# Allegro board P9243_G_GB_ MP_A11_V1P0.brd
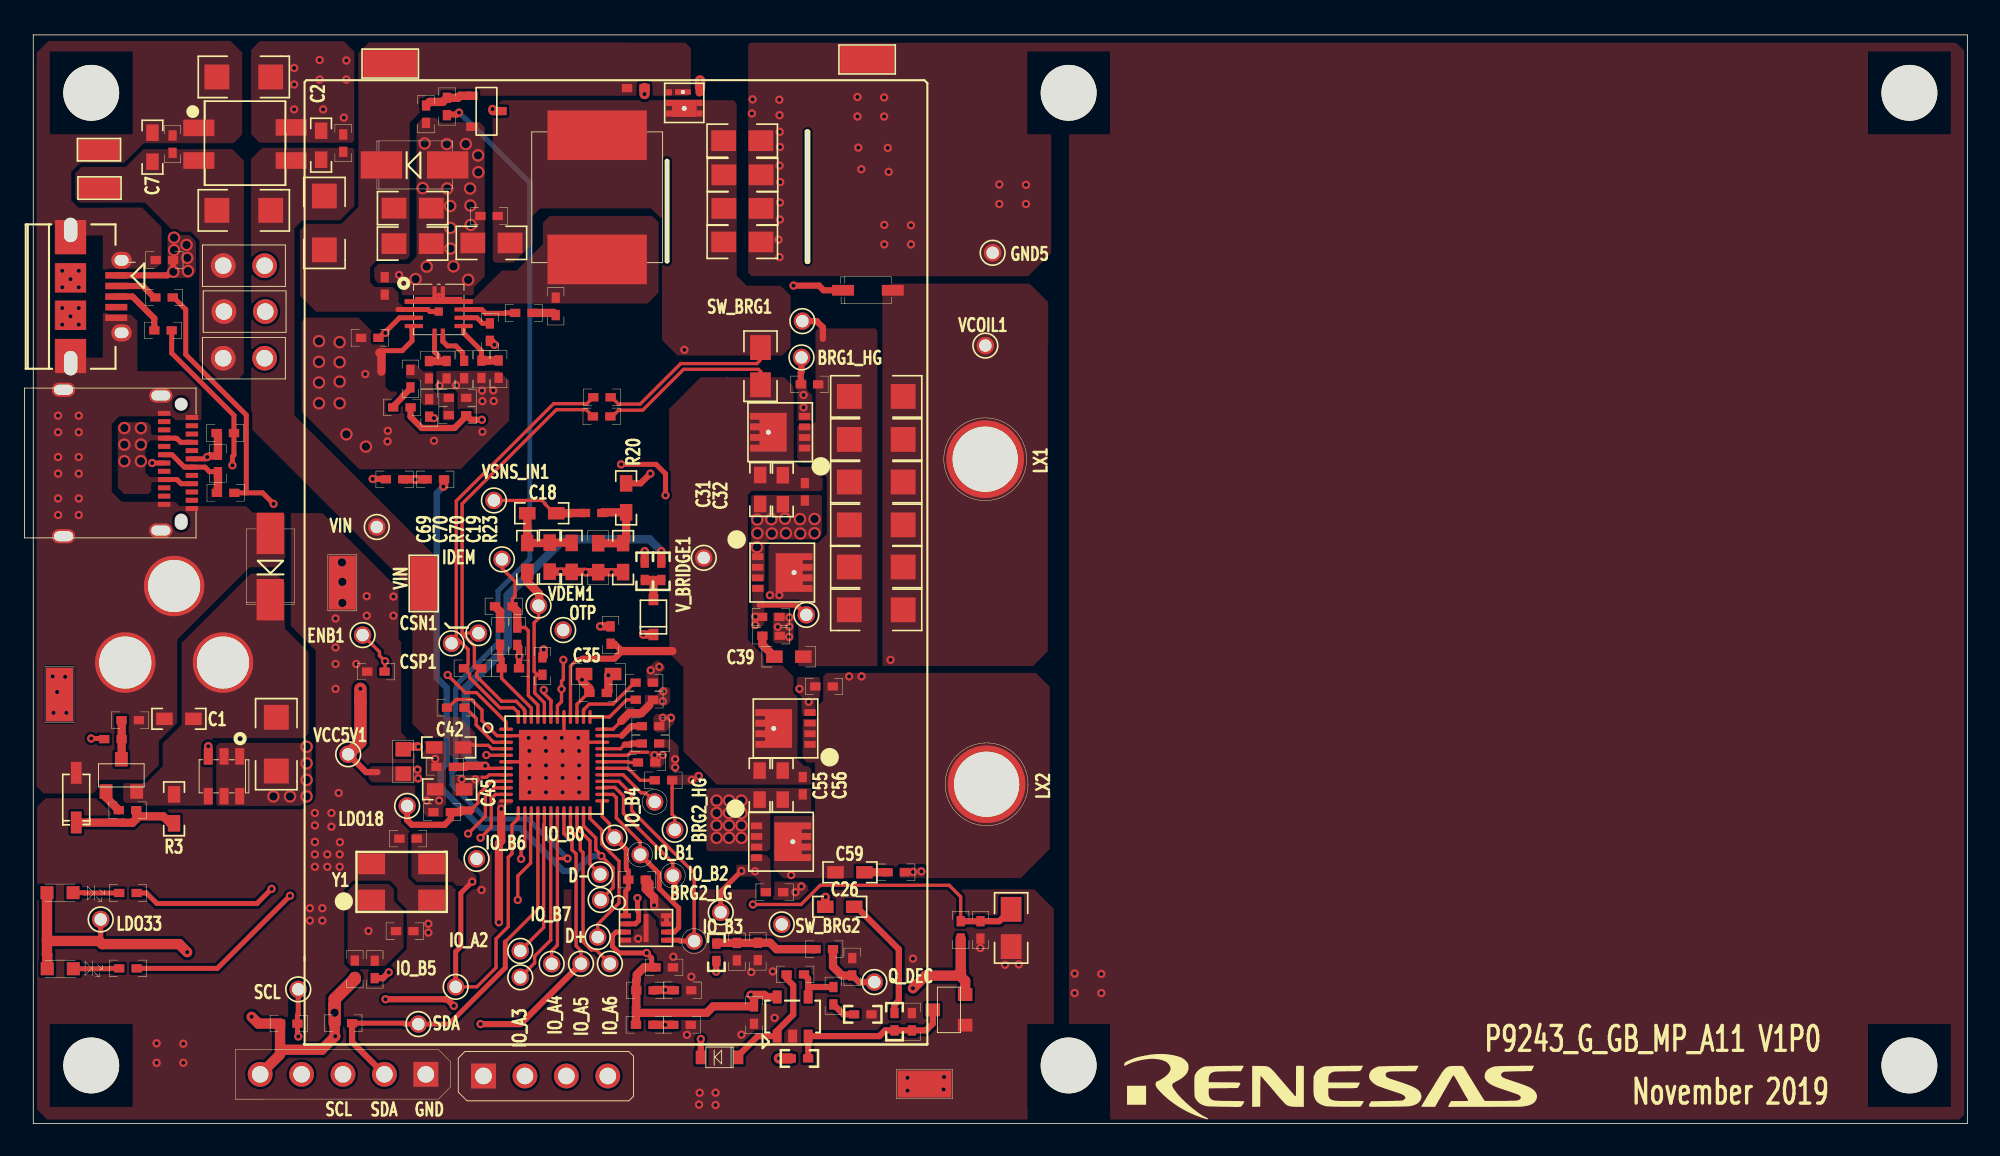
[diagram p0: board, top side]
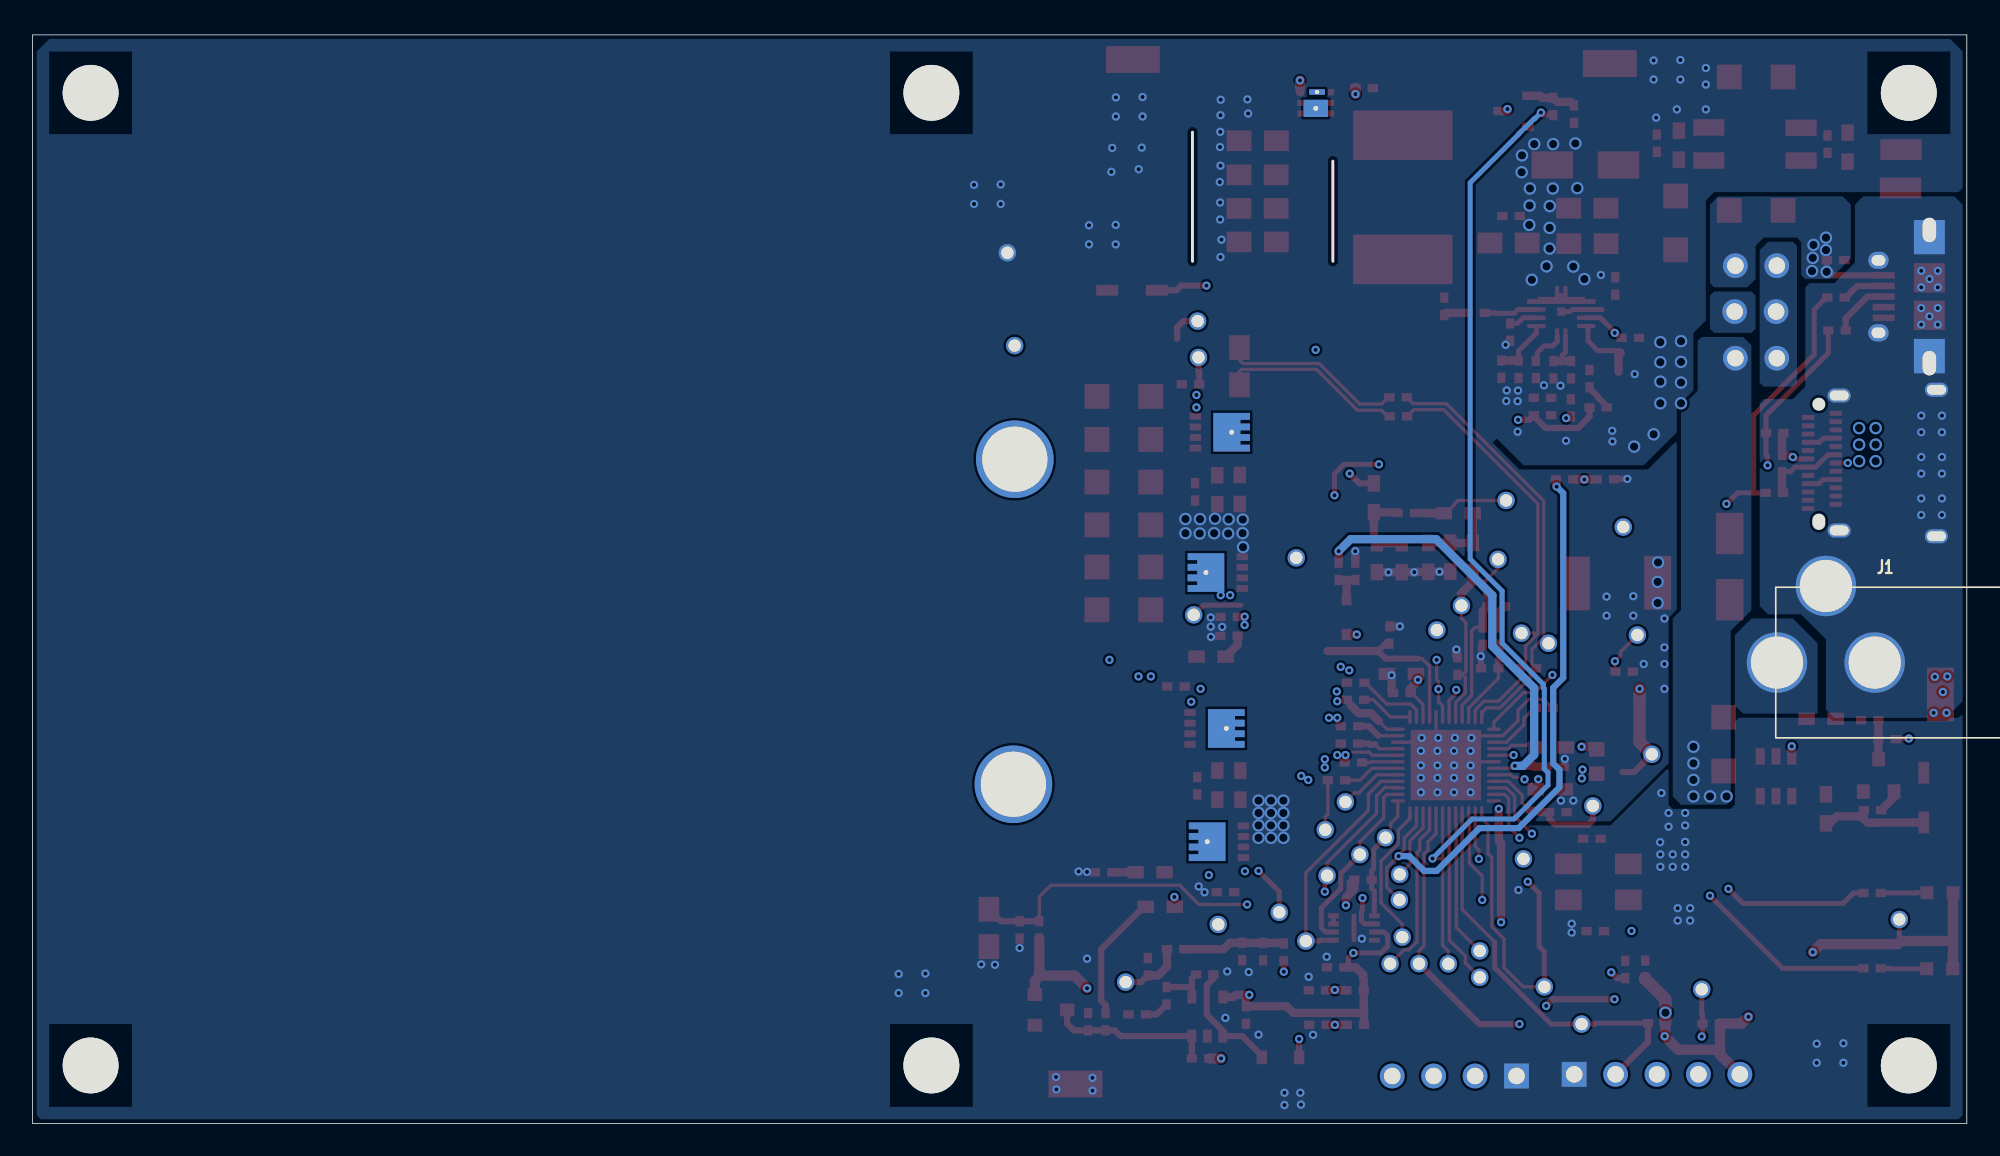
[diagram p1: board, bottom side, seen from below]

Outline 118.62 x 66.8 mm; copper layers: TOP, L1, L2, BOTTOM. Coordinates in mm from the lower left corner of the outline.
Outline path: 0,66.8 0,0 118.62,0 118.62,66.8 0,66.8

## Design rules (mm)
constraint set DEFAULT: min track width 0.152
nets with their own width: min track width 0.508; nets GND

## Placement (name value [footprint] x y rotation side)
BK_VIN  TP  [TEST_PT_SM_135X70]  21.9 65.04 0 top
BRG1_HG  PTH_TP  [TEST_PT30DPAD]  47.12 47.01 0 top
BRG1_LG  PTH_TP  [TEST_PT30DPAD]  47.41 31.21 0 top
BRG2_HG  PTH_TP  [TEST_PT30DPAD]  39.34 18.02 0 top
BRG2_LG  PTH_TP  [TEST_PT30DPAD]  42.16 12.95 0 top
C1  0.1uF  [0603]  8.93 24.83 180 top
C2  10uF  [0603]  17.66 60.03 270 top
C3  0.1uF  [0402]  19.01 60.16 270 top
C4  22uF  [0805]  23.27 56.17 0 top
C5  0.1uF  [0402]  21.56 51.4 270 top
C6  22uF  [0805]  23.27 53.99 0 top
C7  10uF  [0603]  7.31 59.91 270 top
C8  0.1uF  [0402]  8.54 60.1 90 top
C9  0.1uF  [0402]  32.04 50.14 270 top
C10  22uF  [0805]  28.1 54.04 180 top
C11  0.1uF  [0402]  27.95 55.68 180 top
C12  0.1uF  [0402]  28.01 48.56 270 top
C13  NP  [0402]  27.49 46.28 270 top
C14  NP  [0402]  25.35 46.26 270 top
C15  0.1uF  [0402]  26.43 46.27 270 top
C16  0.1uF  [0402]  22.16 39.53 0 top
C18  22nF  [0603]  31.19 37.44 180 top
C19  5.6nF  [0603]  34.65 34.72 90 top
C20  680p  [0402]  31.23 28.07 270 top
C21  22nF  [0402]  28.86 31.73 180 top
C22  22uF  [0805]  43.5 56.15 0 top
C23  22uF  [0805]  43.5 58.21 0 top
C24  22uF  [0805]  43.48 60.31 0 top
C25  22uF  [0805]  43.49 54.1 0 top
C26  220pF  [0603]  49.46 13.29 0 top
C27  5.6nF  [0402]  43.15 10.54 90 top
C28  56pF  [0402]  29.26 27.93 180 top
C29  680pF  [0402]  29.68 29.9 270 top
C30  0.1uF  [0402]  35.41 29.97 270 top
C31  10uF  [0603]  44.58 38.9 90 top
C32  10uF  [0603]  45.97 38.89 90 top
C33  0.1uF  [0402]  47.32 38.76 90 top
C34  0.1uF  [0402]  34.64 26.42 180 top
C35  10uF  [0603]  34.67 27.58 180 top
C36  2.2nF  [0402]  50.23 9.61 270 top
C37  1uF  [0402]  26.95 27.93 180 top
C38  0.1uF  [0402]  37.48 26 0 top
C39  22nF  [0603]  46.34 28.65 0 top
C40  0.1uF  [0402]  44.2 6.65 90 top
C42  10uF  [0603]  25.48 23.07 0 top
C43  1uF  [0402]  25.91 25.51 180 top
C44  100nF  [1206]  51.7 44.61 180 top
C45  10uF  [0603]  25.54 20.5 0 top
C46  0.1uF  [0402]  37.62 22.15 180 top
C47  100nF  [1206]  51.7 41.97 180 top
C48  100nF  [1206]  51.7 39.36 180 top
C49  100nF  [1206]  51.7 36.73 180 top
C50  1uF  [0402]  25.26 21.89 0 top
C51  100nF  [1206]  51.7 34.14 180 top
C52  NP  [1206]  51.7 31.52 180 top
C53  1uF  [0402]  25.08 19.1 0 top
C55  10uF  [0603]  44.55 20.76 90 top
C56  10uF  [0603]  45.96 20.76 90 top
C57  0.1uF  [0402]  47.19 20.72 90 top
C59  22nF  [0603]  50.09 15.41 180 top
C60  18pF  [0402]  22.99 17.48 0 top
C61  18pF  [0402]  22.78 11.8 180 top
C66  0.1uF  [0402]  38.7 9.58 180 top
C67  0.1uF  [0402]  58.09 11.88 90 top
C68  0.1uF  [0402]  8.05 52.98 180 top
C69  22nF  [0603]  30.29 34.73 270 top
C70  5.6nF  [0603]  31.67 34.75 90 top
C71  NP  [0402]  23.14 45.7 270 top
C72  0.1uF  [0402]  50.88 6.69 180 top
CSN1  PTH_TP  [TEST_PT30DPAD]  27.3 30.09 0 top
CSP1  PTH_TP  [TEST_PT30DPAD]  25.65 29.46 0 top
D1  DDZ20BSF-7  [SOD123]  2.64 19.99 270 top
D2  BAV21W-7-F  [SOD123]  51.19 51.13 180 top
D4  1N4148  [SOD-323]  43.23 4.05 180 top
D5  SMAJ20CA-13-F  [SMAJ20CA]  14.54 34.17 270 top
D6  SMAJ20CA-13-F  [SMAJ20CA]  23.39 58.82 180 top
D8  SBAT54SLT1G  [SOT-23]  57.15 6.03 90 top
D9  PMEG4005EJ  [SOD323F]  38.04 31.08 90 top
D+  PTH_TP  [TEST_PT30DPAD]  34.62 11.44 0 top
D-  PTH_TP  [TEST_PT30DPAD]  34.78 15.28 0 top
ENB1  PTH_TP  [TEST_PT30DPAD]  20.2 29.97 0 top
GND  TP  [TEST_PT_SM100X50]  4.03 59.76 90 top
GND1  TP  [TEST_PT_SM_135X70]  51.14 65.29 0 top
GND2  TP  [TEST_PT_SM_135X70]  18.96 33.18 90 top
GND3  TP  [TEST_PT_SM_135X70]  54.66 2.42 0 top
GND4  TP  [TEST_PT_SM_135X70]  1.61 26.32 90 top
GND5  PTH_TP  [TEST_PT30DPAD]  58.84 53.43 0 top
IDEM  PTH_TP  [TEST_PT30DPAD]  28.75 34.62 0 top
IO_A2  PTH_TP  [TEST_PT30DPAD]  29.87 10.59 0 top
IO_A3  PTH_TP  [TEST_PT30DPAD]  29.87 8.97 0 top
IO_A4  PTH_TP  [TEST_PT30DPAD]  31.79 9.79 180 top
IO_A5  PTH_TP  [TEST_PT30DPAD]  33.59 9.8 180 top
IO_A6  PTH_TP  [TEST_PT30DPAD]  35.37 9.8 180 top
IO_B0  PTH_TP  [TEST_PT30DPAD]  35.65 17.54 0 top
IO_B1  PTH_TP  [TEST_PT30DPAD]  37.22 16.5 90 top
IO_B2  PTH_TP  [TEST_PT30DPAD]  39.23 15.21 90 top
IO_B3  PTH_TP  [TEST_PT30DPAD]  40.53 11.19 90 top
IO_B4  PTH_TP  [TEST_PT30DPAD]  38.11 19.73 90 top
IO_B5  PTH_TP  [TEST_PT30DPAD]  25.91 8.38 180 top
IO_B6  PTH_TP  [TEST_PT30DPAD]  27.19 16.24 0 top
IO_B7  PTH_TP  [TEST_PT30DPAD]  34.8 13.72 0 top
J1  AC_Adapter  [CONN_POWER_JACK5_5MM]  11.64 28.28 180 bottom
J2  USB Type C  [USB-C12401610E4]  9.07 40.53 270 top
J3  SIP con  [SIP-4]  27.62 2.91 0 top
J4  68000-105HLF  [SIP5]  24.08 3.01 180 top
J11  5P  [USB_MICRO_AB]  2.29 50.74 270 top
J13  JMP  [SIP2]  14.19 46.96 180 top
J14  JMP  [SIP2]  14.23 49.82 180 top
J15  JMP  [SIP2]  14.19 52.64 180 top
L1  ACM4520  [EMI_TDK_ACM4520L]  12.98 60.16 90 top
L2  TBD  [1206]  17.86 55.26 270 top
L3  10uH  [5X5-10X10]  34.59 56.83 90 top
L4  4.7uH  [L0603]  22.69 22.21 90 top
LDO18  PTH_TP  [TEST_PT30DPAD]  22.93 19.48 0 top
LDO33  PTH_TP  [TEST_PT30DPAD]  4.14 12.52 0 top
LED1  LED  [0603_DIODE]  1.64 14.16 180 top
LED2  LED  [0603_DIODE]  1.66 9.49 180 top
LX1  PTH_TP  [TP_TXCOIL]  58.38 40.76 0 top
LX2  PTH_TP  [TP_TXCOIL]  58.47 20.81 0 top
NOREF  -  [unnamed]  63.5 63.25 0 top
NOREF#2  -  [#2]  0 0 90 top
NOREF#3  -  [unnamed]  63.5 3.56 0 top
NOREF#4  -  [#2]  0 66.64 0 top
NOREF#5  -  [#2]  66.37 -0.28 0 top
NOREF#6  -  [#2]  28.02 19.37 0 top
NOREF#7  -  [#2]  39.45 18.86 90 top
NOREF#8  -  [unnamed]  115.06 3.56 0 top
NOREF#9  -  [unnamed]  3.56 3.56 0 top
NOREF#10  -  [unnamed]  115.06 63.25 0 top
NOREF#11  -  [unnamed]  3.56 63.25 0 top
OTP  PTH_TP  [TEST_PT30DPAD]  32.5 30.28 0 top
Q1  SIA449DJ-T1-GE3  [SC70_6LD_FET]  39.93 62.63 180 top
Q2  Si3417  [SOT-23-6]  11.7 21.3 180 top
Q4  2N7002  [SOT23_3]  27.8 62.13 0 top
Q5  DMG7430LFG  [POWERDI3333_8LD_FET]  45.81 42.42 180 top
Q6  DMG7430LFG  [POWERDI3333_8LD_FET]  45.93 33.8 0 top
Q7  DMG7430LFG  [POWERDI3333_8LD_FET]  46.14 24.24 180 top
Q8  DMG7430LFG  [POWERDI3333_8LD_FET]  45.86 17.29 0 top
Q10  MMBT4403/SOT  [SOT-23]  4.47 20.37 0 top
Q_DEC  PTH_TP  [TEST_PT30DPAD]  51.59 8.67 0 top
R1  0  [1206]  14.91 23.27 270 top
R2  0  [1206]  12.92 56.03 0 top
R3  150  [0603]  8.64 19.3 270 top
R4  100K  [0402]  36.96 63.54 0 top
R5  10k  [0402]  5.78 19.22 180 top
R6  91K  [0402]  5.95 24.75 0 top
R7  10  [0402]  30.09 49.74 0 top
R8  100K  [0402]  24.09 61.93 270 top
R9  0  [1206]  12.92 64.22 0 top
R11  150K  [0402]  26.02 43.46 180 top
R12  30k  [0402]  24.27 46.25 270 top
R13  18K  [0402]  24.28 43.91 270 top
R14  3.3K  [0402]  24.66 39.53 180 top
R15  30k  [0402]  28.54 46.29 270 top
R16  5.1K  [0402]  26.02 44.53 0 top
R18  0  [0402]  11.78 42.37 0 top
R19  10k  [0402]  34.37 37.46 0 top
R20  2.4K  [0603]  36.36 38.39 270 top
R21  0  [0402]  11.8 38.7 0 top
R22  10  [0402]  34.88 44.56 0 top
R23  200K  [0603]  36.17 34.72 90 top
R24  NP  [0402]  11.33 40.5 270 top
R25  10  [0402]  34.86 43.39 0 top
R26  0.02  [0805]  44.6 46.47 270 top
R28  10k  [0402]  28.63 29.91 90 top
R30  18.2k  [0402]  44.44 10.55 90 top
R31  2K  [0402]  48.51 10.69 0 top
R35  22  [0402]  37.47 27.05 0 top
R36  100K  [0402]  47.61 45.36 0 top
R38  22  [0402]  41.9 10.5 270 top
R39  0  [0402]  45.25 29.93 180 top
R40  22  [0402]  37.86 24.38 0 top
R41  1K  [0402]  21.01 27.73 0 top
R42  100K  [0402]  45.23 31.08 180 top
R43  1K  [0402]  5.81 14.14 0 top
R44  22  [0402]  38.65 21.06 0 top
R45  100K  [0402]  48.5 26.82 180 top
R46  680  [0402]  5.81 9.52 0 top
R47  22  [0402]  37.86 23.31 0 top
R48  100K  [0402]  45.46 14.19 0 top
R49  0  [0402]  52.93 15.41 180 top
R50  5.1K  [0402]  19.02 6.15 0 top
R52  5.1K  [0402]  15.67 6.13 0 top
R57  100K  [0402]  37.03 14.96 180 top
R58  20K  [0402]  37.52 8.17 180 top
R59  10k  [0402]  39.82 8.17 180 top
R60  10k  [0402]  56.88 11.88 90 top
R61  10k  [0402]  37.5 6.05 180 top
R62  10k  [0402]  39.79 6.05 180 top
R68  0  [0402]  7.96 48.67 180 top
R69  0  [0402]  8.02 50.68 180 top
R70  47k  [0603]  33.02 34.73 90 top
R79  NP  [0402]  22.61 43.94 0 top
R80  0  [0402]  4.89 23.58 0 top
R82  10k  [0402]  53.89 6.24 270 top
R84  1M  [0402]  20.94 9.45 270 top
R85  5.1K  [0402]  19.72 9.46 90 top
R88  0  [0402]  25.37 62.41 90 top
R93  40.2k  [0402]  46.74 9.14 0 top
R94  10k  [0402]  49.07 7.84 270 top
R95  10k  [0402]  20.64 48.21 0 top
R98  220  [0402]  52.82 6.24 270 top
R99  4.7K  [0402]  38.52 33.88 270 top
R100  825  [0402]  37.5 33.88 270 top
R101  10k  [0402]  46.99 3.99 180 top
SCL  PTH_TP  [TEST_PT30DPAD]  16.25 8.23 0 top
SDA  PTH_TP  [TEST_PT30DPAD]  23.62 6.1 0 top
SW_BRG1  PTH_TP  [TEST_PT30DPAD]  47.17 49.24 0 top
SW_BRG2  PTH_TP  [TEST_PT30DPAD]  45.91 12.21 0 top
T1  TP  [8X250UNPLATED]  38.87 55.98 90 top
T2  TP  [8X320UNPLATED]  47.49 56.87 90 top
TH_COIL1  NP  [0805]  59.97 12 270 top
U1  MP2229  [MP_2229]  24.87 49.95 0 top
U3  P9243-GB  [SOCKETQFN_48_6X6_0P4]  31.95 21.99 0 top
U4  MCP6021  [SOT23-5]  46.57 6.56 90 top
U7  W25X40CLUXIG  [USON_2X3_8LD]  37.58 11.99 0 top
V_BRIDGE1  PTH_TP  [TEST_PT30DPAD]  41.12 34.71 0 top
VCC5V1  PTH_TP  [TEST_PT30DPAD]  19.32 22.65 0 top
VCOIL1  PTH_TP  [TEST_PT30DPAD]  58.39 47.73 0 top
VDEM1  PTH_TP  [TEST_PT30DPAD]  30.99 31.78 0 top
VIN  PTH_TP  [TEST_PT30DPAD]  21.07 36.6 0 top
VIN1  TP  [TEST_PT_SM_135X70]  23.95 33.14 90 top
VIN_SEL  TP  [TEST_PT_SM100X50]  4.06 57.4 90 top
VSNS_IN1  PTH_TP  [TEST_PT30DPAD]  28.25 38.23 0 top
Y1  8MHz  [ECX-53B]  22.59 14.82 0 top

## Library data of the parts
BK_VIN BRG1_HG BRG1_LG BRG2_HG BRG2_LG CSN1 CSP1 D+ D- ENB1 GND GND1-GND5 IDEM IO_A2-IO_A6 IO_B0-IO_B7 LDO18 LDO33 LX1 LX2 OTP Q_DEC SCL SDA SW_BRG1 SW_BRG2 V_BRIDGE1 VCC5V1 VCOIL1 VDEM1 VIN VIN1 VIN_SEL VSNS_IN1 = PTH
C1 C8 C68 = C
C2-C7 C9-C11 C13-C16 C18-C40 C42-C53 C55-C57 C59 C61 C66 C67 C69-C72 = CAP: tolerance: 10%
C12 = CAP NP
C60 = CAP: tolerance: 5%
D1 = DIO_ZEN_1
D2 D4 D9 = DIODE_1
D5 D6 = DIO_ZEN_0
D8 = BAT54S/SOT
J1 = CON2_9
J2 = USB Type C_0
J3 = 68000-105HLF_1
J4 = 68000-105HLF
J11 = MICRO USB AB_5
J13-J15 = HEADER 1x2
L1 = TDK_EMI_4520
L2-L4 = INDUCTOR
LED1 LED2 = LED_0
Q1 = SiA445EDJ_0
Q2 = NDS0610/SOT_6
Q4 = 2N7002_0
Q5-Q8 = MOSFET_P_SO8
Q10 = MMBT4403/SOT
R1-R9 R11-R16 R18-R25 R28 R30 R31 R35 R36 R38-R50 R52 R57-R62 R68-R70 R79 R80 R82 R84 R85 R88 R93-R95 R98-R101 = RESISTOR
R26 = RESISTOR_1
T1 T2 = TP_0
TH_COIL1 = THERMISTOR 2
U1 = MP2229_3
U3 = P9239_14
U4 = NCV2003
U7 = w25x40cl
Y1 = CRYSTAL_3

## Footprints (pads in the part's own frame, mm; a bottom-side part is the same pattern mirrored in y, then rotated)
5X5-10X10
  rect 3.048x6.096 smd: 1(-3.81,0) 2(3.81,0)
8X250UNPLATED
  oval 6.299x0.152 hole 6.35x0.203 unplated: (0,0)
8X320UNPLATED
  oval 8.077x0.152 hole 8.128x0.203 unplated: (0,0)
0402
  rect 0.635x0.508 smd: 1(-0.533,0) 2(0.533,0)
0603
  rect 1.016x0.762 smd: 1(-0.889,0) 2(0.889,0)
0603_DIODE
  rect 0.8x0.8 smd: 1(-0.8,0) 2(0.8,0)
0805
  rect 1.524x1.27 smd: 1(-1.143,0) 2(1.143,0)
1206
  rect 1.524x1.524 smd: 1(-1.651,0) 2(1.651,0)
CONN_POWER_JACK5_5MM
  round 3.708 hole 3.2: 1(0,0) 2(5.994,0) 3(3,4.699)
ECX-53B
  rect 1.651x1.27 smd: 1(-1.841,-1.105) 2(1.841,-1.105) 3(1.841,1.105) 4(-1.841,1.105)
EMI_TDK_ACM4520L
  rect 1.016x1.905 smd: 1(0.94,2.819) 2(-1.067,2.819) 3(-1.067,-2.845) 4(0.965,-2.845)
L0603
  rect 0.899x0.95 smd: 1(-0.749,0) 2(0.749,0)
MP_2229
  custom 0.273x0.273 smd: 1(0,0.889)
  rect 1.118x0.254 smd: 2(-1.524,0.508) 3(-1.524,0) 4(-1.524,-0.508) 5(-1.524,-1.016) 8(1.524,-1.016) 9(1.524,-0.508) 10(1.524,0) 11(1.524,0.508)
  rect 0.254x0.914 smd: 6(-0.254,-1.626) 7(0.254,-1.626)
  rect 0.508x0.508 smd: 15(0,-0.127)
POWERDI3333_8LD_FET
  rect 0.699x0.419 smd: 1(-1.5,0.975) 2(-1.5,0.325) 3(-1.5,-0.325) 4(-1.5,-0.975) 6(0.254,0.889) 7(0.254,0) 8(0.381,-0.762)
  custom 0.562x0.562 hole 0.305: 5(0.725,0)
SC70_6LD_FET
  rect 0.376x0.381 smd: 1(-0.938,0.65) 2(-0.938,0) 3(-0.938,-0.65) 4(0.938,-0.65) 5(0.938,0) 6(0.938,0.65)
  rect 0.97x0.335 hole 0.254: 7(0.08,-0.668)
  rect 1.501x1.052 hole 0.305: 8(0,0.335)
SIP2
  round 1.52 hole 1.016: 1(0,0) 2(2.54,0)
SIP5
  rect 1.524x1.524 hole 1.016: 1(0,0)
  round 1.524 hole 1.016: 2(2.54,0) 3(5.08,0) 4(7.62,0) 5(10.16,0)
SIP-4
  rect 1.524x1.524 hole 1.016: 1(0,0)
  round 1.524 hole 1.016: 2(2.54,0) 3(5.08,0) 4(7.62,0)
SMAJ20CA
  rect 2.54x1.676 smd: 1(-2.032,0) 2(2.032,0)
SOCKETQFN_48_6X6_0P4
  oval 0.864x0.203 smd: 1(-2.95,2.2) 2(-2.95,1.8) 3(-2.95,1.4) 4(-2.95,1) 5(-2.95,0.6) 6(-2.95,0.2) 7(-2.95,-0.2) 8(-2.95,-0.6) 9(-2.95,-1) 10(-2.95,-1.4) 11(-2.95,-1.8) 12(-2.95,-2.2) 25(2.95,-2.2) 26(2.95,-1.8) 27(2.95,-1.4) 28(2.95,-1) 29(2.95,-0.6) 30(2.95,-0.2) 31(2.95,0.2) 32(2.95,0.6) 33(2.95,1) 34(2.95,1.4) 35(2.95,1.8) 36(2.95,2.2)
  oval 0.203x0.864 smd: 13(-2.2,-2.95) 14(-1.8,-2.95) 15(-1.4,-2.95) 16(-1,-2.95) 17(-0.6,-2.95) 18(-0.2,-2.95) 19(0.2,-2.95) 20(0.6,-2.95) 21(1,-2.95) 22(1.4,-2.95) 23(1.8,-2.95) 24(2.2,-2.95) 37(2.2,2.95) 38(1.8,2.95) 39(1.4,2.95) 40(1,2.95) 41(0.6,2.95) 42(0.2,2.95) 43(-0.2,2.95) 44(-0.6,2.95) 45(-1,2.95) 46(-1.4,2.95) 47(-1.8,2.95) 48(-2.2,2.95)
  rect 4.318x4.318 smd: 49(0,0)
SOD123
  rect 1.346x0.66 smd: 1(-1.525,0) 2(1.525,0)
SOD323F
  rect 0.7x0.6 smd: 1(1.075,0) 2(-1.075,0)
SOD-323
  rect 0.635x0.838 smd: 1(0,0) 2(2.286,0)
SOT23-5
  rect 0.8x0.55 smd: 1(-1.2,0.95) 2(-1.2,0) 3(-1.2,-0.95) 4(1.2,-0.95) 5(1.2,0.95)
SOT23_3
  rect 0.711x0.508 smd: 1(-0.889,0.94) 2(-0.889,-0.965) 3(0.889,0)
SOT-23
  rect 0.787x0.889 smd: 1(0,0) 2(1.88,0) 3(0.94,1.981)
SOT-23-6
  rect 0.559x1.016 smd: 1(-0.965,-1.219) 2(0,-1.219) 3(0.965,-1.219) 4(0.965,1.219) 5(0,1.219) 6(-0.965,1.219)
TEST_PT30DPAD
  round 1.067 hole 0.762: 1(0,0)
TEST_PT_SM100X50
  rect 1.27x2.54 smd: 1(0,0)
TEST_PT_SM_135X70
  rect 3.302x1.651 smd: 1(0,0)
TP_TXCOIL
  round 4.762 hole 4: 1(0,0)
unnamed
  round 3.683 hole 3.429 unplated: (0,0)
USB-C12401610E4
  round 0.813 hole 0.762 unplated: (-3.607,0)
  oval 1.016x0.813 hole 0.965x0.762 unplated: (3.607,0)
  rect 0.305x0.762 smd: A1(-2.794,0.66) A2(-2.286,0.66) A3(-1.778,0.66) A4(-1.27,0.66) A5(-0.762,0.66) A6(-0.254,0.66) A7(0.254,0.66) A8(0.762,0.66) A9(1.27,0.66) A10(1.778,0.66) A11(2.286,0.66) A12(2.794,0.66) B1(2.54,-1.041) B2(2.032,-1.041) B3(1.524,-1.041) B4(1.016,-1.041) B5(0.508,-1.041) B6(0,-1.041) B7(-0.508,-1.041) B8(-1.016,-1.041) B9(-1.524,-1.041) B10(-2.032,-1.041) B11(-2.54,-1.041) B12(-3.048,-1.041)
  oval 0.864x1.422 hole 0.61x1.168: M1(-4.14,-1.245) M2(4.14,-1.245) M3(-4.496,-7.214) M4(4.496,-7.214)
USB_MICRO_AB
  rect 0.4x1.35 smd: 1(-1.3,2.8) 2(-0.65,2.8) 3(0,2.8) 4(0.65,2.8) 5(1.3,2.8)
  oval 1.05x1.25 hole 0.65x0.85: 6(-2.225,3.125) 7(2.225,3.125)
  rect 2.1x1.9 hole 1.5x0.825: 8(4.088,0) 9(-4.088,0)
  rect 1.8x1.9 smd: 10(-1.15,0) 11(1.15,0)
USON_2X3_8LD
  rect 0.66x0.305 smd: 1(-1.253,0.75) 2(-1.253,0.25) 3(-1.253,-0.25) 4(-1.253,-0.75) 5(1.253,-0.75) 6(1.253,-0.25) 7(1.253,0.25) 8(1.253,0.75)
  rect 0.305x1.727 smd: 9(0,0)

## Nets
GND: C2.1 C3.1 C4.2 C5.1 C6.2 C10.2 C11.2 C12.2 C13.2 C14.2 C15.2 C16.1 C19.1 C20.1 C22.2 C23.2 C24.2 C25.2 C27.1 C28.1 C29.2 C30.1 C31.1 C32.1 C33.1 C34.1 C35.1 C36.1 C40.1 C42.1 C43.2 C45.1 C50.1 C53.1 C55.1 C56.1 C57.1 C60.1 C61.1 C66.1 C67.1 C70.1 C72.1 D6.1 D8.1 GND1.1 GND2.1 GND3.1 GND4.1 GND5.1 J3.1 J4.1 L1.4 Q4.2(S) Q6.1 Q6.2 Q6.3(S_3) Q8.1 Q8.2 Q8.3(S_3) R8.2 R9.2 R15.2 R16.2 R23.1 R30.1 R39.1 R41.1 R42.1 R48.2 R49.1 R59.1 R62.1 R70.1 R82.1 R95.1 R100.1 TH_COIL1.2 U1.1 U1.5 U3.2 U3.6 U3.34 U3.41 U3.49 U4.2(VSS) U7.4 U7.9 Y1.2 Y1.4
GND_SEL: C1.2 C7.1 C8.2 C68.2 D1.1 D5.1 GND.1 J1.2 J1.3 J2.A1 J2.A12 J2.B1 J2.B12 J2.M1 J2.M2 J2.M3 J2.M4 J11.5 J11.6 J11.7 J11.8 J11.9 J11.10 J11.11(SHIELD) L1.1 R6.2 R9.1
VCC_5V: C34.2 C35.2 C45.2 L4.1 U3.8(VIN_LDO) U3.39 VCC5V1.1
VIN: C2.2 C3.2 C42.2 L1.3 L2.1 R2.2 U3.4 VIN.1 VIN1.1
VIN_SEL: C7.2 C8.1 J13.2 J14.2 J15.2 L1.2 R2.1 VIN_SEL.1
BK_ADJ: IO_B7.1 R14.1 U3.23
BK_EN: IO_B4.1 R95.2 U1.4 U3.29
BK_FB: C71.1 R11.2 R12.2 R13.1 R16.1
BK_SW: C9.1 L3.1 U1.2 U1.11
BK_VIN: BK_VIN.1 C4.1 C5.2 C6.1 D6.2(C) L2.2 Q1.4 Q1.7(S2) R4.1 U1.3 U1.15
BK_VO: C10.1 C11.1 C22.1 C23.1 C24.1 C25.1 L3.2 Q1.1 Q1.2 Q1.5 Q1.6 Q1.8 R11.1 R22.2 R26.1 R79.2
BYP_EN: IO_A4.1 R88.1 U3.19
D+: D+.1 R18.2 R68.1 U3.24
D-: D-.1 IO_A5.1 R21.2 R69.1 U3.20 U3.22
FOD_ADJ: IO_A2.1 J3.4 R58.1 R59.2 U3.17
GPIO_B0: IO_B0.1 R57.2 U3.25 U7.1
GPIO_B1: IO_B1.1 U3.26 U7.6
GPIO_B2: IO_B2.1 U3.27 U7.2
GPIO_B3: IO_B3.1 U3.28 U7.5
IO_B5: C60.2 IO_B5.1 R84.2 U3.13 Y1.3
IO_B6: C61.2 IO_B6.1 R84.1 R85.2 U3.14 Y1.1
ISNS_IN: C21.1 C29.1 IDEM.1 U3.45
ISNS_OUT: C28.2 R28.1 U3.46
LDO18: C53.2 LDO18.1 U3.9
LDO33: C40.2 C50.2 C66.2 D8.2 J3.2 J4.5 LDO33.1 LED1.2 LED2.2 R50.1 R52.1 R57.1 R58.2 R60.1 R61.2 R85.1 R99.1 R101.2 U3.7 U3.12 U4.5 U7.3(WP#) U7.7 U7.8
LED1: R43.2 U3.10
LED2: R46.2 U3.11
LED_PAT: IO_A3.1 J3.3 R61.1 R62.2 U3.18
OTP: C67.2 OTP.1 R60.2 TH_COIL1.1 U3.42
Q_DEC: C36.2 Q_DEC.1 R31.2 U3.43
SCL: J4.3 R52.2 SCL.1 U3.15
SDA: J4.2 R50.2 SDA.1 U3.16
SW_BRG1: C38.2 C39.2 C44.2 C47.2 C48.2 C49.2 C51.2 C52.2 D9.2(C) Q5.1 Q5.2 Q5.3(S_3) Q6.5 Q6.6 Q6.7 Q6.8 R36.2 SW_BRG1.1 U3.36
SW_BRG2: C46.1 C59.2 LX2.1 Q7.1 Q7.2 Q7.3(S_3) Q8.5 Q8.6 Q8.7 Q8.8 R45.1 SW_BRG2.1 U3.32
VBRIDGE: C30.2 C31.2 C32.2 C33.2 C55.2 C56.2 C57.2 Q5.5 Q5.6 Q5.7 Q5.8 Q7.5 Q7.6 Q7.7 Q7.8 R25.2 R26.2 U3.40 V_BRIDGE1.1
N16652621: ENB1.1 R41.2 U3.1
N16652729: C43.1 U3.3
N16653274: L4.2 U3.5
N16655473: IO_A6.1 U3.21
N16659261: R47.1 U3.33
N16659636: R40.1 U3.35
N16659684: C38.1 U3.37
N16659705: R35.1 U3.38
N16664846: C20.2 C69.2 U3.44 VDEM1.1
N16665508: C19.2 R19.2 R20.2 R23.2
N16665538: C18.1 R19.1 VSNS_IN1.1
N16667873: C21.2 R28.2
N16670694: C26.1 C44.1 C47.1 C48.1 C49.1 C51.1 C52.1 D2.1 LX1.1 VCOIL1.1
N16680668: BRG2_LG.1 Q8.4 R47.2 R48.1
N16723656: BRG2_HG.1 Q7.4 R44.2 R45.2
N16805925: C37.1 CSN1.1 R25.1 U3.47
N16810685: R44.1 U3.30
N16818106: BRG1_HG.1 Q5.4 R35.2 R36.1
N16965449: C39.1 R39.2
N16982515: C27.2 R30.2 R31.1 R38.1
N17016599: C46.2 U3.31
N17018728: LED1.1(CATHODE) R43.1
N17018730: LED2.1(CATHODE) R46.1
N17099224: C16.2 R13.2 R14.2
N17141402: BRG1_LG.1 Q6.4 R40.2 R42.2
N17178990: C37.2 CSP1.1 R22.1 U3.48
N17250859: J2.A4 J2.A9 J2.B4 J2.B9(VBUS3) J14.1
N17250883: J2.A6 J2.B6 R18.1 R24.1
N17250901: J2.A7 J2.B7 R21.1 R24.2
N17268068: C14.1 R12.1 U1.6
N17268072: C12.1 U1.9(VCC)
N17268076: C13.1 R15.1 U1.8
N17270513: C15.1 U1.7
N17315318: R7.1 U1.10
N17315646: C9.2 R7.2
N17332852: Q1.3 Q4.3 R4.2
N17332943: Q4.1 R8.1 R88.2
N17336529: D4.1 R93.1 U4.1
N17336905: R93.2 R94.1 U4.4
N17349437: D8.3 R82.2 R98.2 R101.1 U4.3
N17356356: C1.1 D5.2(C) J1.1 Q2.4(S) Q10.2(E) R1.1 R3.1
N17356362: J13.1 Q2.1 Q2.2 Q2.5 Q2.6 R1.2
N17356424: D1.2(C) R3.2 R5.1
N17396839: D2.2(C) R20.1
N17401756: J11.3 R68.2
N17401772: J11.2 R69.2
N17401780: C68.1 J11.1 J15.1
N17411593: C18.2 C69.1 C70.2 R70.2
N17454558: C71.2 R79.1
N17455754: Q10.3 R6.1 R80.2
N17492375: Q10.1 R5.2
N17512349: C26.2 R98.1
N17615155: D9.1 R99.2 R100.2
N17625470: D4.2(C) R38.2
N17645274: C72.2 R94.2
N169656100: C59.1 R49.2
N173631550: Q2.3 R80.1

Pads without a net: J2 A2 A3 A5 A8 A10 A11 B2 B3 B5 B8 B10 B11; J4 4; J11 4

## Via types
v1: diameter 0.508, hole 0.254, TOP to BOTTOM, 270 vias
v2: diameter 0.762, hole 0.508, TOP to BOTTOM, 72 vias

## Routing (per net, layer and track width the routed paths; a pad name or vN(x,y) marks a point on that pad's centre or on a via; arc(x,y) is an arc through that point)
GND: length 33.9
  TOP w0.203: 31.75,22.19 30.15,23.79 U3.2 28.45,23.79 27.52,24.72 27.52,25.36 26.87,26.02 25.95,26.02 25.44,25.51 C43.2 ; 31.75,22.19 U3.6 ; 31.75,22.19 U3.49 32.55,22.59 ; 32.55,22.59 33.35,23.39 U3.34 ; 32.55,22.59 U3.41
  TOP w0.305: 21.24,47.3 21.36,47.42 22.63,47.42 23.23,48.02 23.23,48.82 U1.5
  TOP w0.381: C28.1 29.79,28.65 v1(29.81,28.66) 29.81,29.24 C29.2 ; C16.1 21.6,39.55 v1(20.82,39.55)
  TOP w0.508: 21.36,46.14 21.36,47.18 21.24,47.3 21.32,47.3 21.34,47.27 21.34,47.22 ; R100.1 v1(37.5,35.12) ; v2(18.96,31.94) GND2.1 v2(18.96,33.23) ; v1(28.28,47.78) 28.04,48.03 C12.2 ; C34.1 35.28,26.52 v1(35.28,27.5) 35.48,27.5 C35.1 ; C30.1 v1(34.77,30.51) ; C20.1 31.3,28.67 v1(31.3,29.08) ; C70.1 33,33.86 R70.1 33.87,33.85 v1(33.88,33.83) C19.1 36.17,33.83 R23.1
  vias: v1(1.19,27.43) v1(1.25,25.2) v1(1.46,26.48) v1(1.96,27.41) v1(2.03,25.2) v1(7.57,4.92) v1(7.57,3.72) v1(9.2,4.89) v1(9.2,3.72) v1(16,64.77) v1(16,63.75) v1(16,62.23) v1(16.97,13.21) v1(16.97,12.45) v1(17.27,19.05) v1(17.27,18.29) v1(17.27,17.27) v1(17.27,17.27) v1(17.27,16.51) v1(17.27,15.75) v1(17.57,65.26) v1(17.57,64.06) v1(17.73,13.21) v1(17.73,12.45) v1(17.78,62.23) v1(18.03,16.51) v1(18.03,15.75) v1(18.29,19.05) v1(18.29,18.21) v1(18.54,30.99) v1(18.54,29.21) v1(18.54,28.19) v1(18.54,26.67) v1(18.73,20.28) v1(18.81,17.26) v1(18.8,16.51) v1(18.8,15.75) v1(19.05,61.72) v1(19.2,65.23) v1(19.2,64.06) v1(19.81,28.19) v1(20.36,45.99) v1(20.45,32.35) v1(20.45,31.16) v1(21.75,42.51) v1(21.73,41.85) v1(22.09,32.33) v1(22.09,31.16) v1(22.44,52.07) v1(24.13,19.81) v1(24.23,12.26) v1(24.23,11.71) v1(24.58,41.89) v1(24.65,22.37) v1(24.92,45.27) v1(24.89,19.81) v1(25.93,45.3) v1(27.52,44.98) v1(27.55,44.32) v1(27.55,42.45) v1(27.5,14.33) v1(28.21,44.99) v1(28.24,44.33) v1(30.38,23.66) v1(30.43,22.86) v1(30.43,21.97) v1(30.43,21.21) v1(30.43,20.32) v1(31.4,23.66) v1(31.45,22.86) v1(31.45,21.97) v1(31.45,21.21) v1(31.45,20.32) v1(32.34,33.85) v1(32.41,23.66) v1(32.46,22.86) v1(32.46,21.97) v1(32.46,21.21) v1(32.46,20.32) v1(33.43,23.66) v1(33.48,22.86) v1(33.48,21.97) v1(33.48,21.21) v1(33.48,20.32) v1(35.47,33.82) v1(37.1,11.34) v1(39.25,10.23) v1(40.09,5.44) v1(40.36,9) v1(40.83,1.15) v1(40.87,1.88) v1(41.84,1.88) v1(41.84,1.13) v1(43.43,5.45) v1(44.03,9.29) v1(44.12,62.85) v1(44.07,61.98) v1(45.36,9.33) v1(45.47,6.48) v1(45.71,54.23) v1(45.66,30.47) v1(45.75,62.82) v1(45.77,61.87) v1(45.78,60.85) v1(45.8,59.92) v1(45.77,58.78) v1(45.81,57.77) v1(45.79,56.52) v1(45.79,55.47) v1(45.77,53.17) v1(46.37,31.05) v1(46.37,30.48) v1(46.36,29.86) v1(46.75,14.19) v1(47.1,14.54) v1(50.55,62.99) v1(50.55,61.79) v1(50.6,59.88) v1(50.78,58.56) v1(52.18,62.97) v1(52.18,61.79) v1(52.19,55.14) v1(52.19,53.95) v1(52.41,59.87) v1(52.46,58.4) v1(53.62,2.8) v1(53.62,2.01) v1(53.83,55.12) v1(53.83,53.95) v1(53.95,10.11) v1(53.96,15.43) v1(54.47,15.46) v1(55.83,2.09) v1(55.86,2.85) v1(58.09,10.76) v1(59.25,57.62) v1(59.25,56.43) v1(59.6,9.74) v1(60.44,9.76) v1(60.88,57.6) v1(60.88,56.43) v1(63.87,9.2) v1(63.87,8) v1(65.5,9.17) v1(65.5,8) v2(17.53,48.01) v2(17.53,46.74) v2(17.53,45.47) v2(17.53,44.2) v2(18.79,47.94) v2(18.79,46.72) v2(18.79,45.52) v2(18.8,44.2) v2(18.93,34.43) v2(19.2,42.29) v2(20.4,41.53) v2(23.45,51.82) v2(23.88,57.4) v2(24.01,60.14) v2(24.13,52.58) v2(25.37,60.1) v2(25.39,57.38) v2(25.57,56.3) v2(25.58,54.96) v2(25.58,53.69) v2(25.77,52.6) v2(26.53,60.1) v2(26.67,51.77) v2(26.79,57.38) v2(26.81,56.33) v2(26.83,55.14) v2(27.28,59.41) v2(27.3,58.37) v2(41.91,19.81) v2(41.91,19.05) v2(41.91,18.29) v2(41.91,17.53) v2(42.67,19.81) v2(42.67,19.05) v2(42.67,18.29) v2(42.67,17.53) v2(43.43,19.81) v2(43.43,19.05) v2(43.43,18.29) v2(43.43,17.53) v2(44.4,37.06) v2(44.41,36.22) v2(44.39,35.36) v2(45.27,37.08) v2(45.3,36.2) v2(46.11,37.11) v2(46.16,36.22) v2(47.03,37.08) v2(47.04,36.2) v2(47.92,37.09) v2(47.92,36.22)
GND_SEL:
  vias: v1(1.52,43.43) v1(1.52,42.42) v1(1.52,40.89) v1(1.52,39.88) v1(1.52,38.35) v1(1.52,37.34) v1(1.78,52.32) v1(1.78,51.31) v1(1.78,50.04) v1(1.78,49.02) v1(2.29,51.82) v1(2.29,49.53) v1(2.79,52.32) v1(2.79,51.31) v1(2.79,50.04) v1(2.79,49.02) v1(2.79,43.43) v1(2.79,42.42) v1(2.79,40.89) v1(2.79,39.88) v1(2.79,38.35) v1(2.79,37.34)
VCC_5V: length 29.9
  TOP w0.203: C34.2 34.05,26.42 33.35,25.72 U3.39 ; 27.53,21.24 27.81,21.24 27.96,21.39 U3.8
  TOP w0.381: 21.11,21.56 20.41,21.56 VCC5V1.1
  TOP w0.508: C34.2 34.11,26.7 33.66,27.15 v1(33.66,27.23)
  TOP w0.762: v1(20.07,26.67) 20.07,25.91 20.07,25.9 20.07,23.41 VCC5V1.1
  L2 w0.762: v1(23.56,21.71) 23.56,21.22 v1(23.61,21.17) 23.66,21.12 v1(26.28,21.12) 26.29,21.11 v1(27.12,21.11) ; v1(33.66,27.23) 33.32,27.56 27.56,27.56 25.78,25.78 20.95,25.78 v1(20.07,26.67)
VIN: length 2.2
  TOP w0.203: U3.4 28.12,22.99 27.91,23.2 27.01,23.2 26.95,23.27
BK_ADJ: length 38.3
  TOP w0.203: IO_B7.1 35.56,14.48 35.56,15.68 v1(34.85,16.4) 34.84,16.46 34.5,16.79 34.5,17.51 33.75,18.26 U3.23
  TOP w0.508: v1(25.15,39.08) 25.19,39.12 R14.1
  BOTTOM w0.381: v1(25.15,39.08) 24.75,38.68 24.75,27.34 25.36,26.73 25.36,22.09 24.98,21.7 24.98,20.62 27.48,18.12 29.88,18.12 32.51,15.49 33.27,15.49 34.17,16.39 34.26,16.39 34.27,16.4 v1(34.85,16.4)
BK_EN: length 52.2
  TOP w0.152: R95.2 21.18,48.2
  TOP w0.203: U3.29 36.18,21.39 37.29,20.28 37.55,20.28 IO_B4.1
  TOP w0.305: 21.18,48.2 21.5,48.51 21.54,48.51 ; v1(36.05,40.45) 38.2,40.45 38.78,39.87 v1(38.78,38.55) ; 21.54,48.51 22.47,49.44 U1.4 ; 21.54,48.51 v1(21.59,48.51)
  L2 w0.305: IO_B4.1 37.93,19.73 37.34,20.32 37.34,26.14 36.32,27.15 36.32,36.09 v1(38.78,38.55) ; v1(21.59,48.51) 24.89,48.51 26.75,46.65 26.75,42.45 27.31,41.89 35.14,41.89 36.05,40.98 v1(36.05,40.45)
BK_VIN: length 2.6
  TOP w0.305: U1.15 24.33,49.82 24.2,49.95 U1.3 22.36,49.95
BK_VO: length 31.2
  TOP w0.203: R22.2 35.48,44.56 35.9,44.14 37.22,44.14 39.71,46.63 44.38,46.63 44.57,46.82 44.57,47.58 R26.1
  TOP w0.381: v1(27.52,43.18) 26.84,43.18 R11.1 26.55,43.4 25.83,42.68 23.83,42.68 23.14,43.37 R79.2
  L2 w0.381: v1(39.93,47.47) 38.33,47.47 34.04,43.18 v1(27.52,43.18)
BYP_EN: length 64.9
  TOP w0.203: 32.15,16.27 32.16,16.26 v1(32.77,16.26) ; 32.15,16.27 U3.19 ; 32.15,16.27 32.15,10.93 31.79,10.58 IO_A4.1
  TOP w0.381: R88.1 25.42,61.92 25.99,61.92 26.11,62.04 v1(26.12,62.04)
  BOTTOM w0.305: v1(32.77,16.26) 30.34,18.68 27.76,18.68 25.68,20.76 25.68,21.53 25.91,21.76 25.91,26.67 25.97,26.73 25.97,26.95 28.5,29.48 28.5,32.68 30.45,34.63 30.45,57.73 27.49,60.7 27.49,60.72 27.08,61.13 27.06,61.13 26.53,61.66 26.49,61.66 v1(26.12,62.04)
D+: length 77.1
  TOP w0.203: D+.1 34.62,12.22 35.92,13.53 35.92,16.09 34.9,17.12 34.9,17.17 34.86,17.21 34.86,18 34.15,18.71 U3.24
  TOP w0.305: R68.1 8.49,47.27 12.31,43.45 R18.2 12.31,41.01 12.22,40.92 v1(12.22,40.39)
  L2 w0.305: D+.1 33.68,11.44 33.68,11.44 32.95,11.44 32.79,11.6 27.89,11.6 22.27,5.97 16.13,5.97 12.31,9.79 12.31,22.72 13.94,24.36 13.94,38.66 v1(12.22,40.39)
D-: length 100.3
  TOP w0.203: D-.1 34.15,15.91 34.15,17.34 33.35,18.13 U3.22 ; IO_A5.1 33.59,10.59 33.29,10.89 33.29,16.54 33.04,16.8 33.04,17.29 32.55,17.78 U3.20
  TOP w0.305: 13.07,38.7 14.07,38.7 v1(14.74,38.02) ; 13.07,38.7 R21.2 ; 13.07,38.7 13.07,43.47 9.35,47.19 9.35,49.95 8.62,50.68 R69.1
  TOP w0.381: v1(25.79,7.21) 25.39,7.62 25.26,7.62 25.26,7.62 v1(21.6,7.62) ; v1(27.43,6.1) 29.89,6.1 IO_A5.1
  L2 w0.305: v1(14.74,38.02) 14.58,38.02 14.4,37.85 14.4,24.05 12.9,22.56 12.9,9.96 15.91,6.95 17.2,6.95 17.87,7.62 v1(21.6,7.62) 21.72,7.62 27.22,13.12 31.77,13.12 33.94,15.28 D-.1
  L2 w0.381: v1(25.79,7.21) 26.2,6.81 26.72,6.81 v1(27.43,6.1)
FOD_ADJ: length 28.2
  TOP w0.203: U3.17 31.35,18.38 31.3,18.33 31.3,12.02 IO_A2.1
  TOP w0.508: 38.75,8.19 38.1,8.19 38.08,8.17 R58.1 ; 38.75,8.19 v1(38.76,8.19) ; 38.75,8.19 39.27,8.19 R59.2
  L2 w0.381: J3.4 35.68,2.91 38.22,5.45 39,5.45 39.35,5.8 39.35,7.6 v1(38.76,8.19) 38.21,8.74 31.61,8.74 30.49,9.86 30.49,9.97 IO_A2.1
GPIO_B0: length 7.8
  TOP w0.203: U3.25 34.9,18.83 35.34,18.39 35.34,17.79 35.59,17.54 IO_B0.1
  TOP w0.305: IO_B0.1 36.37,16.81 36.37,15.62 36.5,15.49 R57.2 36.5,14.42 36.33,14.26 36.33,12.75 U7.1
GPIO_B1: length 11.4
  TOP w0.203: IO_B1.1 37.22,17.28 35.76,18.74 35.76,19.99 35.56,20.19 U3.26
  TOP w0.305: U7.6 39.32,11.74 39.59,12.01 39.59,13.22 38.39,14.41 38.39,15.33 IO_B1.1
GPIO_B2: length 13.5
  TOP w0.203: U3.27 34.93,20.62 35.68,20.62 36.2,20.1 36.2,19.03 39.23,15.99 IO_B2.1
  TOP w0.305: IO_B2.1 39.37,15.07 v1(39.37,14.22) ; U7.2 36.93,12.24 37.12,12.44 37.12,12.98 37.06,13.05 v1(37.06,13.83)
  L2 w0.305: v1(37.06,13.83) 37.45,14.22 v1(39.37,14.22)
GPIO_B3: length 14.4
  TOP w0.203: U3.28 35.92,20.99 36.7,20.21 36.7,19.21 40.53,15.38 IO_B3.1
  TOP w0.305: U7.5 39.64,11.24 39.69,11.19 IO_B3.1
IO_B5: length 29.2
  TOP w0.203: U3.13 29.75,18.71 29.36,18.33 29.36,16.56 29.13,16.33 29.13,12.07 28.38,11.33 28.38,9.56 27.21,8.38 IO_B5.1
  TOP w0.305: IO_B5.1 25.91,10.54 26.23,10.86 26.23,14.14 v1(26.92,14.83)
  TOP w0.381: v1(21.81,9.27) 21.45,8.92 R84.2
  L2 w0.381: v1(26.92,14.83) 25.83,14.83 21.81,10.81 v1(21.81,9.27)
IO_B6: length 14.1
  TOP w0.203: v1(29.92,16.23) 29.92,16.77 30.15,17 U3.14
  L2 w0.203: v1(29.92,16.23) 27.98,16.23 27.97,16.24 IO_B6.1
  L2 w0.381: IO_B6.1 24.99,16.24 v1(20.56,11.81)
ISNS_IN: length 11
  TOP w0.203: C21.1 29.39,32.22 29.55,32.38 29.55,33.26 28.75,34.06 28.75,34.26 28.75,34.27 IDEM.1 ; U3.45 30.95,25.67 30.36,26.26 30.36,30.24 30.17,30.43 C29.1
  TOP w0.508: C21.1 29.68,31.44 C29.1
ISNS_OUT: length 5.2
  TOP w0.203: C28.2 28.73,27.32 30.55,25.49 U3.46
  TOP w0.381: C28.2 28.73,28.5 28.63,28.59 R28.1
LDO18: length 8.7
  TOP w0.203: 26.81,19.21 27.27,19.66 27.27,20.15 28.11,20.99 U3.9
  TOP w0.381: C53.2 25.61,18.71 25.23,18.33 23.21,18.33 22.93,18.61 LDO18.1
  TOP w0.508: C53.2 26.16,19.1 26.26,19.21 26.81,19.21
LDO33: length 156.3
  TOP w0.203: v1(27.72,21.94) 27.87,21.79 U3.7
  TOP w0.305: C66.2 37.92,9.82 37.92,10.16 v1(37.62,10.46) 35.93,10.46 35.52,10.87 35.52,11.53 35.74,11.74 U7.3 ; 4.04,11.2 4.14,11.29 LDO33.1 ; U7.7 U7.8
  TOP w0.508: 37.79,14.16 37.79,14.73 R57.1 37.56,14.38 37.79,14.16 ; 37.79,14.16 38.08,13.87 v1(38.08,13.38) ; 36.97,6.78 36.97,7.14 36.98,7.16 R58.2 36.98,8.8 37.02,8.84 37.02,9.13 37.47,9.58 C66.2 ; 36.97,6.78 36.97,6.78 41.3,6.78 41.7,7.19 C40.2 44.2,7.69 v1(44.01,7.89) 44.84,7.89 44.97,7.76 U4.5 ; 36.97,6.78 R61.2 ; C50.2 26.5,21.89 26.56,21.94 v1(27.72,21.94) ; v1(28.7,19.3) 28.7,17.34 28.56,17.19 v1(28.56,12.35) ; R99.1 v1(38.52,35.12)
  TOP w0.635: v1(13.39,6.54) 13.81,6.13 R52.1 15.14,4.52 ; J4.5 15.14,4.23 15.14,4.52 ; R60.1 56.88,9.4 56.9,9.38 56.9,9 ; 15.14,4.52 17.7,4.52 v1(18.52,5.35) 18.49,5.38 R50.1 ; R101.2 v1(45.73,3.99) ; 56.9,9 56.83,9.07 54.73,9.07 v1(53.95,8.29) ; 56.9,9 57.15,8.75 D8.2 ; 0.84,11.25 0.84,10.36 0.86,10.34 LED2.2 ; 0.84,11.25 LED1.2 ; 0.84,11.25 0.9,11.2 4.04,11.2 4.23,11 8.95,11 v1(9.44,10.51)
  TOP w0.762: v2(18.48,6.79) 18.48,7.27 18.49,7.28 ; 18.49,7.28 18.49,7.63 19.72,8.86 R85.1 ; 18.49,7.28 R50.1
  L2 w0.381: 46.62,7.29 46.7,7.37
  L2 w0.508: 27.94,21.59 27.94,21.72 v1(27.72,21.94)
  L2 w0.635: v1(13.39,6.54) 12.9,7.04 12.9,7.05 v1(9.44,10.51) ; v2(18.48,6.79) 21.97,6.79 27.52,12.35 v1(28.56,12.35) 34.11,12.35 34.33,12.56 37.25,12.56 v1(38.08,13.38) 38.08,10.92 v1(37.62,10.46) ; v1(18.52,5.35) 20.23,3.64 20.23,2.17 20.88,1.52 28.77,1.52 J3.2 ; v1(28.7,19.3) 28.29,19.72 28.29,21.24 27.94,21.59 ; v1(45.73,3.99) 46.62,4.88 46.62,7.29 ; v1(44.01,7.89) 46.18,7.89 46.7,7.37 53.02,7.37 v1(53.95,8.29)
  BOTTOM w0.508: v1(38.52,35.12) 37.78,35.85 32.54,35.85 29.1,32.41 29.1,29.29 26.53,26.72 26.53,22.62 27.21,21.94 v1(27.72,21.94)
LED1: length 26.6
  TOP w0.203: v1(26.67,17.78) 27.73,18.84 27.73,20.08 28.24,20.59 U3.10
  TOP w0.305: v1(14.62,14.4) 13.72,13.5 7.58,13.5 6.94,14.14 R43.2
  L2 w0.305: v1(26.67,17.78) 24.61,17.78 21.92,15.09 15.85,15.09 15.15,14.4 v1(14.62,14.4)
LED2: length 28.1
  TOP w0.203: U3.11 28.34,20.19 28.09,19.94 28.09,18.18 v1(27.43,17.53)
  TOP w0.305: R46.2 11.29,9.52 v1(15.75,13.97)
  L2 w0.305: v1(15.75,13.97) 16.33,14.55 22.12,14.55 24.63,17.06 26.96,17.06 v1(27.43,17.53)
LED_PAT: length 30.9
  TOP w0.203: U3.18 31.75,17.92 31.74,17.91 31.74,11.25 30.75,10.27 30.75,9.85 IO_A3.1
  TOP w0.381: v1(38.75,6.05) 38.74,6.04 38.08,6.04 38.07,6.05 R61.1
  TOP w0.508: R61.1 38.03,6.05 v1(38.75,6.05) R62.2
  L2 w0.381: IO_A3.1 30.71,8.12 37.85,8.12 38.75,7.22 v1(38.75,6.05) 38.05,6.05 36.02,4.02 33.8,4.02 J3.3
OTP: length 44.5
  TOP w0.203: U3.42 32.15,25.63 32.4,25.88 v1(32.4,26.65) 32.4,27.14 32.51,27.25 v1(32.51,28.45) ; v1(44.14,13.44) 47.09,13.44 48.27,14.61 56.17,14.61 56.88,13.91 R60.2
  TOP w0.381: TH_COIL1.1 59.24,12.41 C67.2 R60.2
  L2 w0.203: v1(44.14,13.44) 43.46,13.44 40.03,16.87 39.01,16.87 36.93,18.95 36.93,24.79 35.21,26.5 33.03,26.5 32.93,26.61 32.93,26.61 32.88,26.65 v1(32.4,26.65) ; v1(32.51,28.45) 32.51,29.48 32.5,29.49 OTP.1
Q_DEC: length 37
  TOP w0.203: v1(31.31,26.61) 31.31,26.39 31.76,25.95 31.76,25.81 31.75,25.81 U3.43
  TOP w0.381: Q_DEC.1 50.64,8.67 C36.2
  TOP w0.508: C36.2 49.59,9.08 49.05,9.62 R31.2
  L2 w0.203: v1(31.31,26.61) 31.78,26.14 35.08,26.14 36.58,24.64 36.58,18.8 38.86,16.51 39.88,16.51 45.21,11.18 48.94,11.18 50.88,9.23 51.03,9.23 Q_DEC.1
SCL: length 28
  TOP w0.203: U3.15 30.55,18.38 30.5,18.33 30.5,15.97 29.72,15.19 v1(29.72,13.72)
  TOP w0.305: SCL.1 16.25,6.71 16.2,6.66 R52.2 16.2,5.39 v1(16.26,5.33)
  L2 w0.305: v1(16.26,5.33) 16.68,5.33 J4.3 ; SCL.1 21.61,8.23 27.1,13.72 v1(29.72,13.72)
SDA: length 25.3
  TOP w0.203: 28.95,11.14 30.95,13.14 U3.16 ; 22.83,6.1 22.78,6.15 22.73,6.15
  TOP w0.305: 28.95,11.14 28.95,9.55 25.5,6.1 SDA.1 22.78,6.1 22.73,6.15 R50.2
  TOP w0.381: J4.2 19.56,4.99 R50.2
SW_BRG1: length 21.5
  TOP w0.203: 36.07,24.7 35.56,24.19 U3.36
  TOP w0.381: SW_BRG1.1 48.05,49.24 48.43,48.85 48.43,48.15
  TOP w0.508: 37.78,25.67 37.29,25.17 36.54,25.17 36.07,24.7 ; D9.2 v1(37.41,30)
  L2 w0.152: 38.61,26.48 v1(38.64,26.51)
  L2 w0.508: v1(37.41,30) 36.96,29.55 36.96,27.43 37.76,26.63 38.51,26.63 v1(38.64,26.51)
  L2 w0.762: v1(45.75,32.42) v1(45.18,32.42) 44.12,32.42 38.61,26.9 v1(38.61,25.91)
SW_BRG2: length 21.7
  TOP w0.203: 37.68,22.78 36.65,22.78 36.46,22.59 U3.32
  L2 w0.203: SW_BRG2.1 45.35,12.77 45.35,14.11 v1(46.48,15.24)
  L2 w0.762: v1(50.8,27.43) v1(50.04,27.43) 49.5,27.97 43.7,27.97 38.33,22.61 v1(38.1,22.61)
  vias: v1(38.61,22.61)
VBRIDGE: length 21.9
  TOP w0.203: 33.68,28.52 33.41,28.52 32.95,28.06 U3.40 ; R25.2 35.52,43.39 35.9,43.77 37.37,43.77 39.88,46.28 44.48,46.28 44.62,46.13 44.62,45.35 R26.2
  TOP w0.381: C30.2 35.66,29.44 36.11,28.99 35.65,28.52 33.68,28.52
  TOP w0.508: 36.11,28.99 39.2,28.99
N16652621: length 12.2
  TOP w0.203: v1(25.42,27.52) 26.5,26.44 27.18,26.44 29,24.62 U3.1 ; ENB1.1 21.24,28.93 21.24,28.71 v1(21.58,28.36) 21.58,27.76 R41.2
  L2 w0.203: v1(25.42,27.52) 24.93,27.52 24.93,27.51 22.43,27.51 v1(21.58,28.36)
N16652729: length 3.7
  TOP w0.203: U3.3 28.23,23.39 27.17,24.45 27.17,24.85 26.51,25.51 C43.1
N16653274: length 6.6
  TOP w0.203: U3.5 27.83,22.59 27.81,22.61 v1(27.79,22.61)
  TOP w0.508: L4.2 22.73,22.96 22.89,23.13 23.61,23.13 v1(23.62,23.11)
  L2 w0.508: v1(23.62,23.11) 27.28,23.11 v1(27.79,22.61)
N16655473: length 10.4
  TOP w0.203: IO_A6.1 34.52,10.65 34.22,10.65 33.72,11.15 33.72,16.62 33.55,16.79 33.55,17.41 32.95,18.01 U3.21
N16659261: length 2.6
  TOP w0.203: 36.28,23.25 36.02,22.99 U3.33
  TOP w0.381: R47.1 36.69,23.31 36.62,23.25 36.28,23.25
N16659636: length 2.7
  TOP w0.203: 36.09,23.79 U3.35
  TOP w0.381: 36.09,23.79 36.58,24.28 36.59,24.28 36.69,24.38 R40.1
N16659684: length 3.2
  TOP w0.203: U3.37 35.34,24.94 36.4,26 C38.1
N16659705: length 4.3
  TOP w0.203: R35.1 36.88,27.05 35.56,25.73 34.11,25.73 33.79,25.42 33.79,25.41 33.75,25.36 U3.38
N16664846: length 10
  TOP w0.203: U3.44 31.35,25.82 30.76,26.41 30.76,27.38 30.92,27.54 ; 30.92,27.54 31.23,27.54 C20.2 ; 30.92,27.54 30.72,27.73 30.72,30.72 30.99,30.99 VDEM1.1
  TOP w0.508: VDEM1.1 31.03,31.82 31.03,32.51 30.29,33.24 C69.2
N16665508: length 5
  TOP w0.508: C19.2 36.17,35.61 R23.2 36.36,35.8 R20.2 34.94,37.5 R19.2
N16665538: length 5.9
  TOP w0.203: C18.1 31.95,37.44 31.4,37.99 31.4,38.03 31.2,38.23 VSNS_IN1.1
  TOP w0.508: C18.1 32.97,37.44 32.98,37.46 R19.1
N16667873: length 1.4
  TOP w0.508: C21.2 28.63,31.42 R28.2
N16670694: length 16.8
  TOP w0.508: v1(48.6,13.9) 48.57,13.88 C26.1
  L2 w0.305: v1(52.58,28.45) 52.58,27.91 48.57,23.91 48.57,14.45 48.6,14.43 v1(48.6,13.9)
N16680668: length 12.9
  TOP w0.305: BRG2_LG.1 42.16,14.22 v1(43.43,15.49)
  L2 w0.762: v1(44.27,15.48) 44.25,15.49 v1(43.43,15.49) 42.67,15.49 41.06,17.11 41.06,18.12 39.37,19.81 v1(39.37,21.84) v1(39.37,22.35)
N16723656: length 14.4
  TOP w0.203: BRG2_HG.1 39.34,18.81 39.18,18.97 39.18,20.57 39.18,20.57 R44.2
  L2 w0.762: v1(47.56,25.87) 46.99,26.45 v1(46.99,26.67) 43.94,26.67 40.82,23.54 v1(40.82,21.32) 40.58,21.08 v1(40.39,21.08)
N16805925: length 27.2
  TOP w0.203: 26.41,29.95 26.54,30.09 CSN1.1 ; 26.41,29.95 26.3,30.06 26.3,38.02 32.08,43.8 33.91,43.8 R25.1 ; 26.41,29.95 27.06,29.31 27.06,28.02 27.11,27.96 27.46,27.96 C37.1 27.19,27.64 27.19,27.44 28.72,25.91 29.61,25.91 30.1,25.42 30.1,25.36 30.15,25.31 U3.47
N16810685: length 3.5
  TOP w0.203: R44.1 37.22,21.06 36.48,21.79 U3.30
N16818106: length 24.4
  TOP w0.381: R36.1 47.07,46.09 47.12,46.13 BRG1_HG.1
  L2 w0.762: v1(37.87,27.81) 38.22,27.81 38.22,28.03 38.27,28.07 38.27,28.09 38.46,28.09 42.67,32.31 42.67,38.1 43.43,38.86 46.23,38.86 47.24,39.88 v1(47.24,43.94) v1(47.24,44.7)
  vias: v1(38.4,28.02)
N16965449: length 1.6
  TOP w0.508: C39.1 44.72,29.38 R39.2
N16982515: length 6.3
  TOP w0.508: R38.1 41.9,11.06 41.88,11.08 43.15,11.08 C27.2 44.42,11.07 R30.2 45.19,11.09 45.58,10.69 R31.1
N17016599: length 2.2
  TOP w0.203: U3.31 36.5,22.19 36.54,22.15 C46.2
N17018728: length 2.8
  TOP w0.305: LED1.1 3.12,14.16 3.14,14.14 R43.1
N17018730: length 2.8
  TOP w0.305: R46.1 4.67,9.52 4.65,9.49 LED2.1
N17099224: length 6
  TOP w0.381: R13.2 24.37,43.29 v1(24.57,43.29)
  TOP w0.508: R14.2 23.47,39.53 v1(23.46,39.52) 23.44,39.53 C16.2
  L2 w0.381: v1(23.46,39.52) 23.86,39.92 23.86,40.12 23.88,40.13 23.88,42.59 v1(24.57,43.29)
N17141402: length 12.5
  TOP w0.305: 44.29,30.79 44.29,30.59 v1(44.29,30.59) ; 44.51,31.8 46.82,31.8 BRG1_LG.1
  L2 w0.762: v1(44.29,31.1) 44.29,31.09 v1(44.29,30.59) 44.18,30.48 43.66,30.48 39.65,26.47 39.65,25.43 v1(39.12,24.89) v1(38.61,24.89)
N17178990: length 27
  TOP w0.203: R22.1 33.96,44.17 31.92,44.17 25.95,38.2 25.95,29.81 ; 25.95,29.81 26.67,29.08 26.67,28.18 C37.2 26.76,27.59 26.76,27.36 28.62,25.5 29.45,25.5 29.75,25.21 U3.48 ; 25.95,29.81 25.67,29.53 25.67,29.48 CSP1.1
N17250859: length 3.6
  TOP w0.305: J2.A9 9.07,39.26 8.82,39.51 J2.B4 ; J2.A4 9.04,41.8 8.8,42.04 8.7,42.04 8.69,42.05 J2.B9
  vias: v2(5.59,42.67) v2(5.59,41.66) v2(5.59,40.64) v2(6.6,42.67) v2(6.6,41.66) v2(6.6,40.64)
N17250883: length 8
  TOP w0.305: J2.B6 v1(7.29,40.53) ; v1(10.67,40.89) 11.19,40.89 R24.1 10.79,41.03 10.54,40.78 J2.A6
  TOP w0.508: R24.1 11.33,42.28 R18.1
  L2 w0.305: v1(7.29,40.53) 9.77,40.53 10.13,40.89 v1(10.67,40.89)
N17250901: length 5
  TOP w0.305: J2.B7 8.51,41.04 9.27,40.28 J2.A7 10.53,40.28 10.81,40 11.29,40 R24.2
  TOP w0.508: R24.2 11.33,39 11.32,38.99 11.32,38.75 R21.1
N17268068: length 2.7
  TOP w0.305: U1.6 24.61,47.34 24.81,47.14 24.81,46.78
  TOP w0.508: R12.1 25.35,46.78 C14.1
N17268072: length 1.8
  TOP w0.305: U1.9 27.21,49.44 27.56,49.09 C12.1
N17268076: length 3.6
  TOP w0.305: C13.1 27.49,47.41 26.39,48.51 U1.8
  TOP w0.508: R15.1 27.9,46.82 27.9,46.82 27.49,46.82 C13.1
N17270513: length 2.4
  TOP w0.305: C15.1 26.34,46.89 26.34,47.29 25.92,47.71 25.4,47.71 25.12,47.99 U1.7
N17315318: length 3.3
  TOP w0.305: U1.10 27.5,49.95 27.74,49.71 28.93,49.71 28.95,49.74 R7.1
N17315646: length 1.5
  TOP w0.508: C9.2 31.91,49.74 R7.2
N17332852: length 15.2
  TOP w0.508: Q1.3 40.89,63.31 40.89,63.56 ; v1(28.17,62.25) 28.17,62.16 28.2,62.13 Q4.3
  TOP w0.635: 40.89,63.56 v1(40.89,64.01) ; R4.2 v1(37.49,63.17)
  L2 w0.635: v1(40.89,64.01) 38.33,64.01 v1(37.49,63.17) 36.57,62.25 v1(28.17,62.25)
N17332943: length 3.1
  TOP w0.508: Q4.1 26.17,63.07 26.04,62.94 R88.2 25.12,62.69 24.31,62.69 R8.1
N17336529: length 7.4
  TOP w0.381: R93.1 46.2,8.88 46.61,8.47 46.61,6.68 45.62,5.7 U4.1 44.44,5.36 43.23,4.15 D4.1
N17336905: length 3
  TOP w0.381: R94.1 47.52,8.37 ; 47.52,8.37 47.52,8.89 R93.2 ; 47.52,8.37 U4.4
N17349437: length 10.2
  TOP w0.381: R101.1 47.52,4.09 U4.3 51.9,5.36 52.25,5.71 R98.2 R82.2 54.76,5.71 55.17,6.12 D8.3
N17356362:
  vias: v2(14.73,20.07) v2(15.75,20.07) v2(16.76,23.11) v2(16.76,22.1) v2(16.76,21.08) v2(16.76,20.07)
N17356424: length 6.9
  TOP w0.508: 6.32,18.68 R5.1 ; 6.32,18.68 6.48,18.84 7.98,18.84 8.4,18.41 R3.2 ; 6.32,18.68 6.08,18.45 5.5,18.45 5.49,18.46 3.36,18.46 3.35,18.47 D1.2
N17396839: length 21.7
  TOP w0.381: R20.1 37.25,39.28 v1(37.85,39.88) ; D2.2 48.48,51.13 48.19,51.41 v1(46.63,51.41)
  L2 w0.381: v1(46.63,51.41) 45.97,50.76 45.97,45.21 45.47,44.7 43.69,44.7 38.86,39.88 v1(37.85,39.88)
N17401756: length 3.6
  TOP w0.381: R68.2 7.43,49.41 6.09,50.74 J11.3
N17401772: length 2.7
  TOP w0.381: J11.2 6.72,51.39 7.43,50.68 R69.2
N17401780: length 4.3
  TOP w0.381: J11.1 8.21,52.04 8.43,52.26 v2(8.59,52.26) 8.58,52.28 C68.1
  vias: v2(8.64,54.36) v2(8.64,53.59) v2(9.4,53.91) v2(9.45,53.12) v2(9.49,52.31)
N17411593: length 4.6
  TOP w0.508: C18.2 30.3,36.51 30.29,36.51 C69.1 31.65,35.62 C70.2 33,35.64 R70.2
N17454558: length 1.7
  TOP w0.381: R79.1 22.07,44 22.66,44.59 22.66,44.63 23.14,45.11 C71.2
N17455754: length 2.4
  TOP w0.508: R6.1 5.42,24.74 R80.2 5.42,22.37 Q10.3
N17492375: length 1.5
  TOP w0.508: Q10.1 4.47,20.01 R5.2
N17512349: length 7.8
  TOP w0.381: C26.2 50.48,13.29 53.08,10.69 53.08,7.54 52.81,7.27 52.81,6.79 R98.1
N17615155: length 2.2
  TOP w0.508: 38.02,33.35 R99.2 ; 38.02,33.35 R100.2 ; 38.02,33.35 38.04,33.34 D9.1
N17625470: length 6.4
  TOP w0.381: v1(41.88,9.31) 41.88,10.01 41.88,10.01 ; D4.2 v1(40.94,5.18)
  TOP w0.508: 41.88,10.01 41.9,10 R38.2
  L2 w0.381: v1(40.94,5.18) 41.88,6.12 v1(41.88,9.31)
N17645274: length 1.5
  TOP w0.381: R94.2 49.68,6.69 C72.2
N169656100: length 1.4
  TOP w0.508: R49.2 50.98,15.41 C59.1
N173631550: length 8.8
  TOP w0.305: R80.1 4.31,23.62 v1(3.56,23.62)
  TOP w0.508: Q2.3 v1(10.73,23.14)
  L2 w0.305: v1(3.56,23.62) 4.03,23.14 v1(10.73,23.14)

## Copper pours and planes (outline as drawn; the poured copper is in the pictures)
GND on TOP: 13.88,60.19 13.37,60.7 13.37,62.86 13.36,62.87 13.36,65.86 13.35,65.87 13.89,66.41 19.05,66.41 19.69,65.77 19.69,64.19 19.69,64.18 19.69,60.32 19.56,60.19
GND on TOP: 0.85,0.24 0.23,0.86 0.23,18.76 0.24,18.76 0.24,19.43 0.66,19.86 0.67,19.86 0.77,19.96 3.88,19.96 4.56,19.27 16.52,19.27 17.32,20.08 17.32,29.02 17.12,29.22 17.11,29.22 15.8,30.54 15.8,37.46 17.75,37.46 22.41,32.79 22.41,29.69 22.57,29.53 22.57,23.99 23.43,23.13 23.43,18.44 26.67,18.44 30.36,14.75 30.36,14.36 43.71,14.36 43.71,14.36 44.34,14.36 44.38,14.32 44.38,13.81 44.47,13.71 45.36,13.71 45.39,13.74 45.39,14.27 45.4,14.28 45.4,14.75 45.5,14.84 47.24,14.84 47.51,14.57 47.51,14.36 60.36,14.36 60.39,14.39 60.42,14.36 61.42,14.36 61.42,14.34 62.59,13.17 62.59,6.05 63.45,6.05 63.52,6.12 63.52,63.17 63.61,63.26 63.61,64.54 62.7,64.54 62.43,64.26 62.43,53.41 61.16,52.14 61.16,52.13 61.02,51.99 61.02,51.99 52.2,51.99 52.18,52 44.06,52 43.85,52.21 43.85,66.2 43.97,66.32 117.93,66.32 118.42,65.83 118.42,0.53 118.12,0.24 66.05,0.24 66.05,1.09 60.99,1.09 60.99,0.24 ; 10 cut-outs
GND on TOP: 20,40.14 16.9,43.24 16.9,43.24 16.46,43.68 16.46,44.52 16.46,44.52 16.46,49.19 16.73,49.45 19.94,49.45 20.88,48.51 20.89,48.51 21.6,47.81 21.6,45.21 21.89,44.92 23.05,44.92 23.31,44.65 23.31,44.04 23.47,43.89 24.93,43.89 24.99,43.82 24.99,42.88 25.1,42.78 25.86,42.78 25.93,42.85 25.93,44.92 25.82,45.03 25.82,45.03 24.81,45.03 24.72,45.13 24.72,45.5 24.72,46.14 24.77,46.19 28.57,46.19 29.19,45.57 29.19,43.13 26.22,40.15 20.94,40.15 20.94,40.14
GND on TOP: 41.68,20.58 47.66,20.58 47.72,20.53 47.72,19.21 47.7,19.21 47.58,19.09 45.23,19.09 45.2,19.06 45.2,16.84 45.18,16.84 45.04,16.7 41.38,16.7 41.28,16.8 41.28,20.43 41.43,20.59 41.68,20.59
GND on TOP: 22.66,50.82 22.6,50.88 22.6,51.25 22.29,51.57 21.14,51.57 20.96,51.75 20.96,51.87 20.91,51.91 20.91,52.49 21.17,52.75 23.06,52.75 23.51,53.2 23.51,61.33 23.52,61.34 23.9,61.72 24.69,61.72 24.96,61.44 27.39,61.44 27.69,61.14 27.69,51.98 27.03,51.32 27.03,50.93 26.93,50.82 26.9,50.82
GND on TOP: 44.13,33.29 44.02,33.4 44.02,36.92 44.03,36.92 44.03,38.45 44.14,38.56 44.2,38.56 44.21,38.57 48.29,38.57 48.37,38.48 48.37,36.59 48.37,36.59 48.37,36.23 48.03,35.89 48,35.89 48.02,35.89 48.02,35.87 47.98,35.83 45.19,35.83 44.86,35.51 44.86,33.35 44.8,33.29
GND on TOP: 25.32,23.33 25.32,18.81 24.14,18.81 23.93,19.02 23.93,21.04 24.04,21.15 24.04,22.38 23.69,22.73 23.69,23.47 25.18,23.47 25.18,23.46
GND on TOP: 45.52,29.46 45.36,29.62 45.36,31.28 45.36,31.28 45.41,31.33 45.42,31.34 46.47,31.34 46.64,31.16 46.64,29.74 46.36,29.46
GND on TOP: 53.21,15.71 54.6,15.71 54.69,15.62 54.69,15.08 54.67,15.07 53.18,15.07 53.12,15.12 53.12,15.64 53.19,15.71
GND on TOP: 29.87,24.08 29.87,19.89 33.93,19.89 33.93,24.08
GND on BOTTOM: 0.51,0.25 0.25,0.51 0.25,25.15 0.51,24.89 13.97,24.89 14.22,24.64 14.22,19.56 14.48,19.3 18.03,19.3 18.29,19.56 18.29,21.84 21.84,18.29 27.69,18.29 27.69,18.54 21.84,18.54 18.29,22.1 18.29,30.99 17.78,31.5 17.78,41.91 19.56,40.13 27.43,40.13 29.08,41.78 28.83,42.04 27.18,40.39 19.81,40.39 17.78,42.42 17.78,43.94 16.76,44.96 16.76,48.51 16,49.28 16,56.64 15.49,57.15 0.51,57.15 0.25,57.4 0.25,65.79 1.02,66.55 117.6,66.55 118.36,65.79 118.36,0.51 118.11,0.25
GND on L1: 0.54,0.25 0.21,0.58 0.21,0.58 0.21,65.06 0.21,65.07 0.21,65.95 0.71,66.45 1.63,66.45 1.63,66.46 117.78,66.46 118.42,65.82 118.42,0.51 118.15,0.25 ; 2 cut-outs
GND on L2: 0.51,0.25 0.25,0.51 0.25,65.53 1.02,66.29 117.86,66.29 118.36,65.79 118.36,0.51 118.11,0.25 ; 16 cut-outs
GND_SEL on TOP: outline of 87 points within 0.18,20.25 15.45,66.44
GND_SEL on BOTTOM: 1.27,24.89 0.25,25.91 0.25,56.39 0.76,56.9 6.35,56.9 6.86,56.39 6.86,52.83 8.13,51.56 9.65,51.56 9.91,51.31 9.91,45.21 10.67,44.45 12.45,44.45 12.7,44.2 12.7,31.75 12.19,31.24 10.16,31.24 8.64,29.72 8.64,25.4 8.13,24.89
VCC_5V on TOP: 22.25,20.94 22.25,20.94 20.79,20.94 20.57,21.15 20.57,21.73 20.75,21.91 22.23,21.91 22.23,21.92 23.76,21.92 23.84,21.84 23.84,21.12 23.66,20.94
VCC_5V on TOP: 25.8,20.1 25.7,20.2 25.7,21.28 25.79,21.37 26.39,21.37 26.4,21.37 27.57,21.37 27.61,21.34 27.61,21.05 27.01,20.45 27.01,20.19 26.93,20.1
VIN on TOP: 25.79,22.36 25.42,22.74 25.42,23.58 25.32,23.68 24.09,23.68 23.25,24.52 23.25,32.75 13.43,42.57 13.44,42.57 13.44,43.62 13.36,43.7 13.36,59.19 13.93,59.76 13.93,59.76 14.05,59.87 19.58,59.87 19.69,59.76 19.69,56.3 18.81,55.42 16.5,55.42 16.02,54.94 16.02,43.44 24.83,34.64 24.89,34.64 24.89,25.27 25.2,24.95 26.15,24.95 26.18,24.92 26.18,24.89 26.48,24.59 26.5,24.59 27.1,23.99 27.1,22.53 26.93,22.36
VIN_SEL on TOP: 10.95,45.71 10.17,46.49 10.17,54.14 10.16,54.14 10.16,54.21 9.66,54.72 9.19,54.72 9.18,54.71 8.64,54.71 6.84,56.51 2.83,56.51 2.83,56.52 2.58,56.77 2.57,56.77 2.57,58.31 2.97,58.7 5.68,58.7 6.76,59.78 9.85,59.78 9.86,59.8 12.2,59.8 12.92,59.07 12.92,56.49 12.92,56.48 12.92,46.02 12.62,45.71
VIN_SEL on BOTTOM: 10.67,54.1 12.19,54.1 12.7,53.59 12.7,45.47 12.45,45.21 10.67,45.21 10.41,45.47 10.41,53.85
BK_FB on TOP: 25.11,43.22 25.11,44.03 25.07,44.07 23.93,44.07 23.76,44.24 23.76,45.49 23.56,45.7 22.96,45.7 22.86,45.8 22.86,46.54 22.91,46.59 23.46,46.59 23.65,46.4 23.66,46.4 23.9,46.15 24.47,46.15 24.52,46.11 24.52,45.01 24.7,44.83 25.76,44.83 25.82,44.78 25.82,43.2 25.77,43.15 25.77,43.15 25.17,43.15
BK_SW on TOP: 22.83,50.31 22.79,50.36 22.79,50.56 22.83,50.61 27,50.61 28.05,51.66 28.06,51.66 28.72,52.32 28.72,52.34 29.64,52.34 31.26,53.96 31.26,55.28 31.67,55.69 37.96,55.69 38.35,55.3 38.35,51 37.67,50.31 37.67,50.31
BK_VIN on TOP: 16.36,52.07 16.36,54.81 16.78,55.23 16.78,55.21 18.91,55.21 19.84,56.14 19.84,56.14 19.94,56.24 19.94,65.67 19.93,65.68 20.59,66.34 36.44,66.34 36.44,66.33 39.99,66.33 40.33,65.99 40.33,63.19 40.2,63.07 27.14,63.07 26.58,62.51 24.11,62.51 24.11,62.42 23.09,61.41 23.09,53.23 22.88,53.02 21.14,53.02 20.66,52.54 20.66,51.61 20.94,51.33 22.05,51.33 22.41,50.97 22.41,50.4 22.76,50.05 22.84,50.05 22.84,49.9 22.75,49.81 17.35,49.81 16.36,50.8
BK_VO on TOP: 39.51,47.12 38.57,48.07 38.57,55.48 37.89,56.15 31.1,56.15 30.64,55.69 30.64,54 29.46,52.83 29.25,52.83 29.23,52.81 29.22,52.82 28.33,52.82 28.19,52.96 28.19,60.98 28.17,60.99 28.17,62.23 28.74,62.79 41.79,62.79 41.79,62.79 42.25,62.79 42.25,62.79 42.94,62.79 43.14,62.58 43.14,52.02 43.76,51.41 45.84,51.41 46.45,50.8 46.45,47.64 45.94,47.12 45.76,47.12 45.76,47.12 40.75,47.12
IO_B5 on TOP: 25.74,17.83 26.05,17.53 26.05,16.31 27.18,15.18 27.18,14.72 27.04,14.58 25.96,14.58 25.72,14.82 23.53,14.82 23.19,15.16 23.19,17.72 23.3,17.83
IO_B6 on TOP: 19.28,14.27 19.7,14.69 21.79,14.69 22.12,14.36 22.12,13.65 22.71,13.07 22.71,10.78 21.59,9.66 19.47,9.66 19.28,9.86
LDO33 on TOP: 38.54,12.07 38.39,12.21 38.39,12.53 38.33,12.59 38.32,12.61 38.06,12.86 38.06,12.87 37.87,13.06 37.87,13.93 38.03,14.09 38.22,14.09 39.15,13.15 39.15,13.14 39.2,13.09 39.2,12.15 39.12,12.07
SW_BRG1 on TOP: 46.92,28.06 46.92,32.15 45.33,32.15 45.09,32.39 45.09,33.41 45.09,33.41 45.09,35.15 45.09,35.15 45.09,35.44 45.27,35.62 48.12,35.62 48.67,36.17 48.67,39.66 48.56,39.77 47.77,40.55 47.12,40.55 46.85,40.82 46.85,42.77 46.99,42.91 47.8,42.91 47.98,43.09 47.98,48.61 48.15,48.79 51.62,48.79 51.77,48.65 51.77,28.09 51.74,28.06
SW_BRG1 on TOP: 37.51,26.26 37.51,25.77 37.63,25.65 38.85,25.65 39.06,25.86 39.06,26.66 38.95,26.78 38.52,26.78 38.52,26.77 38.3,26.55 38.3,26.37 38.3,26.36 38.24,26.3 37.54,26.3
SW_BRG2 on TOP: 37.66,22.86 38.57,22.86 38.71,22.71 38.71,22.06 38.45,21.79 37.96,21.79 37.85,21.91 37.84,21.91 37.82,21.93 37.82,22.52 37.63,22.71 37.61,22.71 37.61,22.81
SW_BRG2 on TOP: 46,15.05 45.41,15.64 45.41,18.81 45.47,18.87 45.47,18.87 47.81,18.87 47.95,19.01 47.95,22.15 47.45,22.15 47.19,22.41 47.19,24.04 47.19,24.04 47.19,24.83 48.15,24.83 48.19,24.87 48.19,25.68 48.44,25.93 48.44,27.42 48.44,27.42 48.67,27.65 61.49,27.65 62.33,26.8 62.34,26.8 62.34,16.88 62.34,16.84 60.56,15.05
